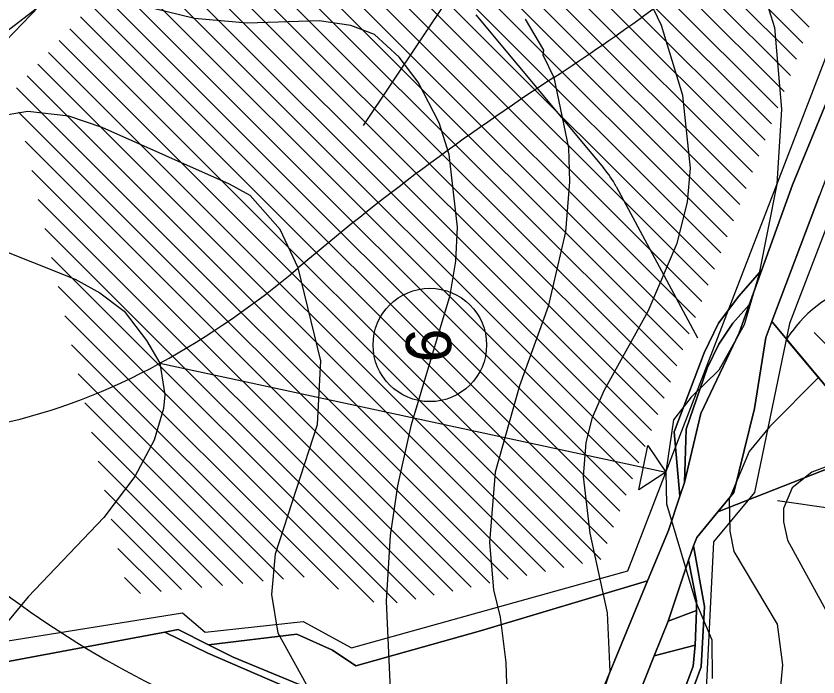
# Model space of a CAD drawing. Extents: x -510989 to -501240, y -1184665 to -1176098.
# Drawn here: x -510017.7 to -509664.3, y -1180562.4 to -1180270.9 of the extents above; entities that cross this region are included whole.
import ezdxf

# ---------------------------------------------------------------- set-up
doc = ezdxf.new("R2010")
doc.units = 0
for name, color, linetype in [('lesni_pozemek', 7, 'Continuous'), ('NAVRH_interakcni_prvky', 7, 'Continuous'), ('NAVRH_rozvodnice', 7, 'Continuous'), ('orna_puda', 7, 'Continuous'), ('ostatni_plocha_x_neplodna_puda', 7, 'Continuous'), ('ostatni_plocha_x_ostatni_komunikace', 7, 'Continuous'), ('ostatni_plocha_x_silnice', 7, 'Continuous'), ('STAV_erozne_ohrozene_plochy', 7, 'Continuous'), ('STAV_odtokove_linie', 7, 'Continuous'), ('STAV_systematicke_odvodneni', 7, 'Continuous'), ('STAV_vyrazne_udolnice', 7, 'Continuous'), ('trvaly_travni_porost', 7, 'Continuous'), ('vrstevnice_01', 7, 'Continuous'), ('vrstevnice_02', 7, 'Continuous')]:
    doc.layers.add(name, color=color, linetype=linetype)

msp = doc.modelspace()

# ---------------------------------------------------------------- linework, layer by layer
at = {"layer": 'lesni_pozemek'}
for points in [[(-509812.99, -1180541.95), (-509739.42, -1180520), (-509769.58, -1180593.16), (-509777.22, -1180619.34), (-509786.94, -1180611.68), (-509795.39, -1180601.71), (-509804.94, -1180595.11), (-509813.79, -1180591.47), (-509819.81, -1180590.05), (-509845.28, -1180577.33), (-509864.98, -1180571.99), (-509893.19, -1180565.46), (-509921.95, -1180553.56), (-509932.82, -1180548.16), (-509893.97, -1180543.48), (-509878.28, -1180550.47), (-509867.93, -1180557.38)], [(-509718.41, -1180548.4), (-509719.28, -1180557.64), (-509722.56, -1180566.21), (-509738.62, -1180583.4), (-509738.62, -1180590.26), (-509745.01, -1180605.17), (-509751.41, -1180616.33), (-509742.05, -1180636.9), (-509765.49, -1180626.89), (-509753.97, -1180597.17), (-509736.42, -1180553.04)]]:
    msp.add_lwpolyline(points, close=True, dxfattribs=at)
msp.add_lwpolyline([(-510036.28, -1180558.37), (-509952.16, -1180542.58), (-509933.25, -1180551.83), (-509896.13, -1180567.82), (-509845.52, -1180580.81), (-509820.72, -1180592.79), (-509809.8, -1180596.02), (-509797.64, -1180602.69), (-509786.79, -1180615.24), (-509778.16, -1180622.56), (-509788.23, -1180657.04), (-509798.56, -1180673.4), (-509807.58, -1180682.98), (-509830.84, -1180699.77), (-509846.4, -1180697.78), (-509862.58, -1180695.7), (-509972.79, -1180679.21), (-509982.76, -1180675.51), (-510000.96, -1180668.76), (-510006.56, -1180666.69), (-510015.53, -1180660.83), (-510023.76, -1180655.45)], dxfattribs=at)
at = {"layer": 'NAVRH_interakcni_prvky'}
for p, q in [((-509815.05, -1180270.35), (-509758.84, -1180337.8)), ((-509753.23, -1180346.1), (-509717.33, -1180412.78))]:
    msp.add_line(p, q, dxfattribs=at)
msp.add_arc((-509797.25, -1180369.81), 50, 28.301, 39.8056, dxfattribs=at)
at = {"layer": 'NAVRH_rozvodnice'}
for centre, radius, start, end in [((-510313.43, -1179479.68), 976.45, 303.06509, 309.14233), ((-509174.82, -1181228.64), 1110.48, 123.06509, 130.32304), ((-510133.02, -1180099.69), 370.29, 298.8563, 310.323), ((-510084.33, -1180188.04), 269.41, 266.556, 298.8563), ((-509762.71, -1180179.15), 433.02, 222.5554, 243.421)]:
    msp.add_arc(centre, radius, start, end, dxfattribs=at)
at = {"layer": 'orna_puda'}
for points in [[(-509653.04, -1180290.71), (-509675.52, -1180345.29), (-509689.08, -1180382.89), (-509699.18, -1180394.47), (-509708.09, -1180406.34), (-509714.44, -1180419.43), (-509727.66, -1180454.24), (-509725.13, -1180482.57), (-509730.24, -1180497.75), (-509739.42, -1180520), (-509812.99, -1180541.95), (-509867.93, -1180557.38), (-509878.28, -1180550.47), (-509893.97, -1180543.48), (-509932.82, -1180548.16), (-509946.28, -1180541.47), (-509952.16, -1180542.58), (-510036.28, -1180558.37)], [(-509637.72, -1180461.75), (-509684.7, -1180405.65), (-509663.64, -1180349.99)]]:
    msp.add_lwpolyline(points, dxfattribs=at)
at = {"layer": 'ostatni_plocha_x_neplodna_puda'}
for points in [[(-509687.34, -1180412.63), (-509684.7, -1180405.65), (-509637.72, -1180461.75), (-509708.44, -1180489.55), (-509701.45, -1180480.97), (-509692.29, -1180443.92)], [(-509717.87, -1180528.83), (-509717.87, -1180533.11), (-509730.35, -1180537.79), (-509721.42, -1180510.79)], [(-509717.87, -1180533.22), (-509718.41, -1180548.4), (-509736.42, -1180553.04), (-509730.35, -1180537.79), (-509717.87, -1180533.11)]]:
    msp.add_lwpolyline(points, close=True, dxfattribs=at)
at = {"layer": 'ostatni_plocha_x_ostatni_komunikace'}
for points in [[(-509699.18, -1180394.47), (-509689.08, -1180382.89), (-509694.62, -1180398.26), (-509701.75, -1180406.39), (-509707.92, -1180415.55), (-509713.15, -1180426.25), (-509722.41, -1180453.1), (-509723.12, -1180476.62), (-509725.13, -1180482.57), (-509727.66, -1180454.24), (-509714.44, -1180419.43), (-509708.09, -1180406.34)], [(-509701.75, -1180406.39), (-509694.62, -1180398.26), (-509699.09, -1180410.64), (-509715.98, -1180446.18), (-509723.12, -1180476.62), (-509722.41, -1180453.1), (-509713.15, -1180426.25), (-509707.92, -1180415.55)], [(-509721.42, -1180510.79), (-509719.09, -1180504.59), (-509714.27, -1180531.29), (-509715.84, -1180557.88), (-509719.49, -1180567.82), (-509735.91, -1180585.38), (-509736.21, -1180592.82), (-509741.34, -1180604.78), (-509747.74, -1180616.58), (-509738.93, -1180638.23), (-509742.05, -1180636.9), (-509751.41, -1180616.33), (-509745.01, -1180605.17), (-509738.62, -1180590.26), (-509738.62, -1180583.4), (-509722.56, -1180566.21), (-509719.28, -1180557.64), (-509718.41, -1180548.4), (-509717.87, -1180533.22), (-509717.87, -1180533.11), (-509717.87, -1180528.83)], [(-509952.16, -1180542.58), (-509946.28, -1180541.47), (-509932.82, -1180548.16), (-509921.95, -1180553.56), (-509893.19, -1180565.46), (-509864.98, -1180571.99), (-509845.28, -1180577.33), (-509819.81, -1180590.05), (-509813.79, -1180591.47), (-509804.94, -1180595.11), (-509795.39, -1180601.71), (-509786.94, -1180611.68), (-509777.22, -1180619.34), (-509778.16, -1180622.56), (-509786.79, -1180615.24), (-509797.64, -1180602.69), (-509809.8, -1180596.02), (-509820.72, -1180592.79), (-509845.52, -1180580.81), (-509896.13, -1180567.82), (-509933.25, -1180551.83)]]:
    msp.add_lwpolyline(points, close=True, dxfattribs=at)
at = {"layer": 'ostatni_plocha_x_silnice'}
for points in [[(-509769.58, -1180593.16), (-509739.42, -1180520), (-509730.24, -1180497.75), (-509725.13, -1180482.57), (-509723.12, -1180476.62), (-509715.98, -1180446.18), (-509699.09, -1180410.64), (-509694.62, -1180398.26), (-509689.08, -1180382.89), (-509675.52, -1180345.29), (-509653.04, -1180290.71), (-509626.86, -1180225.88), (-509599.01, -1180147.29), (-509576.88, -1180084.83), (-509569.47, -1180061.07), (-509562.83, -1180032.49), (-509563.62, -1180023.92), (-509565.24, -1180006.24)], [(-509547.91, -1180014.23), (-509547.11, -1180025.3), (-509546.79, -1180029.63), (-509551.44, -1180058.44), (-509552.27, -1180063.61), (-509560.59, -1180087.35), (-509587.22, -1180149.46), (-509614.94, -1180223.33), (-509641.36, -1180291.15), (-509663.64, -1180349.99), (-509684.7, -1180405.65), (-509687.34, -1180412.63), (-509692.29, -1180443.92), (-509701.45, -1180480.97), (-509708.44, -1180489.55), (-509717.69, -1180500.89), (-509719.09, -1180504.59), (-509721.42, -1180510.79), (-509730.35, -1180537.79), (-509736.42, -1180553.04), (-509753.97, -1180597.17)]]:
    msp.add_lwpolyline(points, dxfattribs=at)
at = {"layer": 'STAV_erozne_ohrozene_plochy'}
for p, q in [((-509830.92, -1180122.86), (-509670.91, -1180282.87)), ((-509823.3, -1180120.58), (-509668.12, -1180275.76)), ((-509838.54, -1180125.14), (-509673.69, -1180289.99)), ((-509853.78, -1180129.7), (-509679.26, -1180304.22)), ((-509846.16, -1180127.42), (-509676.47, -1180297.11)), ((-509861.4, -1180131.98), (-509682.04, -1180311.34)), ((-509876.64, -1180136.54), (-509687.61, -1180325.57)), ((-509869.02, -1180134.26), (-509684.82, -1180318.46)), ((-509884.26, -1180138.81), (-509690.39, -1180332.69)), ((-509899.5, -1180143.37), (-509695.95, -1180346.92)), ((-509891.88, -1180141.09), (-509693.17, -1180339.8)), ((-509907.12, -1180145.65), (-509698.74, -1180354.04)), ((-509922.36, -1180150.21), (-509704.3, -1180368.27)), ((-509914.74, -1180147.93), (-509701.52, -1180361.15)), ((-509929.98, -1180152.49), (-509707.09, -1180375.39)), ((-509945, -1180157.27), (-509712.65, -1180389.62)), ((-509937.6, -1180154.77), (-509709.87, -1180382.5)), ((-509946.52, -1180165.65), (-509715.44, -1180396.73)), ((-509948.04, -1180174.03), (-509718.22, -1180403.85)), ((-509949.56, -1180182.41), (-509721, -1180410.97)), ((-509951.08, -1180190.79), (-509723.79, -1180418.08)), ((-509952.59, -1180199.18), (-509726.57, -1180425.2)), ((-509954.11, -1180207.56), (-509729.35, -1180432.32)), ((-509955.63, -1180215.94), (-509732.14, -1180439.43)), ((-509957.15, -1180224.32), (-509734.92, -1180446.55)), ((-509958.67, -1180232.7), (-509737.7, -1180453.66)), ((-509961.16, -1180240.11), (-509740.49, -1180460.78)), ((-509965.86, -1180245.31), (-509743.27, -1180467.9)), ((-509970.56, -1180250.51), (-509746.05, -1180475.01)), ((-509975.25, -1180255.71), (-509748.84, -1180482.13)), ((-509979.95, -1180260.91), (-509751.62, -1180489.25)), ((-509984.65, -1180266.11), (-509754.4, -1180496.36)), ((-509989.35, -1180271.31), (-509757.19, -1180503.48)), ((-509994.05, -1180276.51), (-509759.97, -1180510.59)), ((-509998.75, -1180281.71), (-509768.13, -1180512.34)), ((-510003.45, -1180286.91), (-509776.29, -1180514.07)), ((-510008.15, -1180292.11), (-509784.45, -1180515.81)), ((-510012.85, -1180297.31), (-509792.61, -1180517.55)), ((-510017.55, -1180302.51), (-509800.77, -1180519.29)), ((-510016.66, -1180313.3), (-509808.93, -1180521.03)), ((-510013.73, -1180326.13), (-509817.09, -1180522.77)), ((-510010.81, -1180338.95), (-509825.25, -1180524.51)), ((-510007.89, -1180351.77), (-509833.41, -1180526.25)), ((-510004.97, -1180364.59), (-509841.57, -1180527.99)), ((-510002.04, -1180377.42), (-509849.73, -1180529.73)), ((-509999.12, -1180390.24), (-509859.97, -1180529.39)), ((-509996.2, -1180403.06), (-509875.61, -1180523.65)), ((-509665.95, -1180410.41), (-509600.61, -1180475.74)), ((-509993.27, -1180415.88), (-509890.76, -1180518.4)), ((-509990.35, -1180428.7), (-509899.77, -1180519.29)), ((-509987.43, -1180441.53), (-509908.77, -1180520.18)), ((-509984.51, -1180454.35), (-509917.78, -1180521.07)), ((-509981.58, -1180467.17), (-509926.79, -1180521.97)), ((-509978.66, -1180479.99), (-509935.8, -1180522.86)), ((-509975.74, -1180492.82), (-509944.8, -1180523.75)), ((-509972.82, -1180505.64), (-509953.81, -1180524.64)), ((-509969.89, -1180518.46), (-509962.82, -1180525.53))]:
    msp.add_line(p, q, dxfattribs=at)
msp.add_lwpolyline([(-509638.07, -1180461.33), (-509678.1, -1180413.53), (-509675.6, -1180409.95)], dxfattribs=at)
msp.add_arc((-509634.61, -1180438.57), 50, 97.035, 145.081, dxfattribs=at)
at = {"layer": 'STAV_odtokove_linie'}
for p, q in [((-509864.65, -1180319.18), (-509702.19, -1180076)), ((-509954.31, -1180424), (-509731.41, -1180472))]:
    msp.add_line(p, q, dxfattribs=at)
msp.add_lwpolyline([(-509739.25, -1180460.23), (-509731.41, -1180472), (-509743.18, -1180479.84)], close=True, dxfattribs=at)
msp.add_circle((-509835.35, -1180415.95), 25, dxfattribs=at)
at = {"layer": 'STAV_systematicke_odvodneni'}
for p, q in [((-509971.55, -1180229.15), (-510029, -1180288.76)), ((-509624.17, -1180268.6), (-509676.84, -1180406.44)), ((-509748.11, -1180515.48), (-509659.01, -1180284.63)), ((-509676.84, -1180406.44), (-509692.27, -1180480.95)), ((-509692.27, -1180480.95), (-509710.35, -1180502.77)), ((-509710.35, -1180502.77), (-509713.82, -1180571.74)), ((-509869.94, -1180549.54), (-509748.11, -1180515.48)), ((-510109.86, -1180560.71), (-509944.41, -1180534.1)), ((-509944.41, -1180534.1), (-509934.31, -1180542.62)), ((-509934.31, -1180542.62), (-509891.22, -1180537.83)), ((-509891.22, -1180537.83), (-509869.94, -1180549.54))]:
    msp.add_line(p, q, dxfattribs=at)
at = {"layer": 'STAV_vyrazne_udolnice'}
msp.add_lwpolyline([(-509476.81, -1180544.93), (-509523.03, -1180536.49), (-509563.62, -1180523.23), (-509610.64, -1180510.78), (-509657.67, -1180488.28), (-509682.18, -1180484.66)], dxfattribs=at)
at = {"layer": 'trvaly_travni_porost'}
msp.add_lwpolyline([(-509719.49, -1180567.82), (-509715.84, -1180557.88), (-509714.27, -1180531.29), (-509719.09, -1180504.59), (-509717.69, -1180500.89), (-509708.44, -1180489.55), (-509637.72, -1180461.75), (-509620.2, -1180483.63), (-509545.52, -1180520.3), (-509475.01, -1180529.87), (-509449.45, -1180521.23), (-509411.24, -1180459.85), (-509368.25, -1180475.22), (-509408.3, -1180507.2), (-509415.15, -1180514.71), (-509421.2, -1180524.49), (-509424.91, -1180535.2), (-509427.22, -1180544.4), (-509426.83, -1180564.36)], dxfattribs=at)
at = {"layer": 'vrstevnice_01'}
for points in [[(-509688.5, -1180260), (-509683.5, -1180276), (-509680.41, -1180312), (-509682.5, -1180345), (-509690.31, -1180385), (-509696.81, -1180407), (-509708, -1180427), (-509720.19, -1180439), (-509727.91, -1180449), (-509731.41, -1180472), (-509731, -1180486), (-509718.31, -1180529), (-509711.09, -1180546), (-509710.91, -1180563)], [(-509793.35, -1180272.25), (-509785.31, -1180286), (-509785.5, -1180288), (-509780.69, -1180298), (-509774.31, -1180329), (-509773.81, -1180344), (-509775.59, -1180366), (-509783.19, -1180399), (-509795.81, -1180434), (-509806.59, -1180472), (-509809.09, -1180503), (-509807.31, -1180524), (-509804.31, -1180536), (-509801.81, -1180556), (-509801.41, -1180570)], [(-510025.5, -1180650), (-510010.59, -1180653), (-510006.41, -1180651), (-509994.59, -1180642), (-509960.69, -1180624), (-509942.41, -1180618), (-509903.41, -1180608), (-509895.5, -1180604), (-509890.09, -1180599), (-509884.09, -1180587), (-509887.31, -1180570), (-509902.19, -1180543), (-509904.91, -1180526), (-509903.41, -1180508), (-509884.91, -1180451), (-509883.41, -1180423), (-509893.41, -1180382), (-509901.31, -1180365), (-509914.59, -1180350), (-509923.59, -1180345), (-509979.81, -1180320), (-509994.5, -1180315), (-510012.5, -1180313), (-510054.5, -1180320)], [(-509648.19, -1180465), (-509667, -1180472), (-509675.69, -1180479), (-509679.5, -1180488), (-509679.5, -1180494), (-509677.69, -1180502), (-509655.91, -1180542)]]:
    msp.add_lwpolyline(points, dxfattribs=at)
at = {"layer": 'vrstevnice_02'}
for points in [[(-509764.09, -1180585), (-509755.91, -1180560), (-509757.09, -1180534), (-509764.69, -1180499), (-509767.59, -1180474), (-509766.41, -1180459), (-509763.69, -1180448), (-509758.5, -1180436), (-509739.09, -1180401), (-509726.31, -1180371), (-509721.81, -1180353), (-509720.5, -1180338), (-509723.81, -1180306), (-509733.19, -1180275), (-509740.41, -1180260)], [(-509852, -1180584), (-509854.41, -1180529), (-509852.69, -1180500), (-509849.41, -1180478), (-509843.41, -1180451), (-509826.41, -1180394), (-509823.91, -1180379), (-509823.09, -1180364), (-509826.81, -1180332), (-509831.31, -1180318), (-509840.5, -1180300), (-509848.91, -1180289), (-509859.81, -1180279), (-509870.19, -1180275), (-509884.19, -1180273), (-509915.81, -1180274), (-509939, -1180272), (-509983.59, -1180261), (-509995.81, -1180262), (-510005.19, -1180265), (-510031.41, -1180285)], [(-510067, -1180357), (-509991.69, -1180387), (-509980.81, -1180393), (-509970.09, -1180401), (-509960.19, -1180414), (-509954.31, -1180424), (-509952.19, -1180438), (-509952.69, -1180444), (-509956.91, -1180458), (-509965.41, -1180474), (-509979, -1180492), (-510012.31, -1180527), (-510021.41, -1180538)], [(-509663.81, -1180430), (-509685.69, -1180452), (-509694.59, -1180463), (-509703.41, -1180484), (-509703.19, -1180498), (-509701.31, -1180507), (-509682.31, -1180539), (-509680, -1180557), (-509680.91, -1180568)]]:
    msp.add_lwpolyline(points, dxfattribs=at)

# ---------------------------------------------------------------- texts
at = {"layer": 'STAV_odtokove_linie'}
msp.add_text('9', height=20, rotation=270, dxfattribs=at).set_placement((-509845.94, -1180408.65))

doc.saveas('drawing.dxf')
